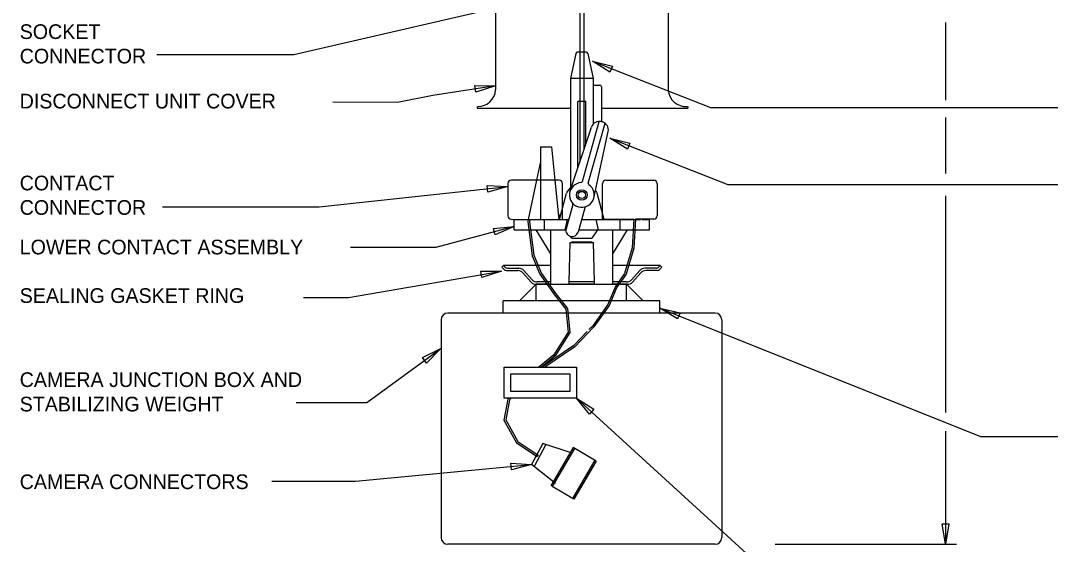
# Model space of a CAD drawing. Extents: x 1299104.6 to 1299141.4, y 239713.3 to 239735.3.
# Drawn here: x 1299120.45 to 1299128.87, y 239721.53 to 239725.82 of the extents above; entities that cross this region are included whole.
import ezdxf

# ---------------------------------------------------------------- set-up
doc = ezdxf.new("R2010")
doc.units = 0
for name, color, linetype in [('DIM TXT', 7, 'Continuous'), ('Level 3', 7, 'Continuous'), ('Level 6', 7, 'Continuous'), ('Level 8', 7, 'Continuous')]:
    doc.layers.add(name, color=color, linetype=linetype)

msp = doc.modelspace()

# ---------------------------------------------------------------- linework, layer by layer
at = {"layer": 'Level 3'}
for p, q in [((1299124.3359, 239726.9924), (1299124.3359, 239725.2509)), ((1299125.7467, 239726.9924), (1299125.7467, 239725.2509)), ((1299124.9918, 239725.55), (1299124.9488, 239725.3448)), ((1299125.0776, 239725.5608), (1299125.005, 239725.5608)), ((1299125.0908, 239725.55), (1299125.1338, 239725.3448)), ((1299125.1338, 239725.3448), (1299124.9488, 239725.3448)), ((1299124.9488, 239725.3448), (1299124.9488, 239724.4533)), ((1299125.1338, 239725.3448), (1299125.1338, 239724.9716)), ((1299125.1338, 239725.2908), (1299125.1878, 239725.2908)), ((1299125.2013, 239725.2773), (1299125.2013, 239724.9922)), ((1299124.1854, 239725.1159), (1299124.1854, 239725.1024)), ((1299124.1854, 239725.1024), (1299124.9488, 239725.1024)), ((1299125.075, 239725.1558), (1299125.0075, 239725.1558)), ((1299125.0075, 239724.6103), (1299125.0075, 239725.1558)), ((1299125.075, 239724.8126), (1299125.075, 239725.1558)), ((1299125.2013, 239725.1024), (1299125.9093, 239725.1024)), ((1299125.9093, 239725.1159), (1299125.9093, 239725.1024)), ((1299124.9436, 239724.4189), (1299125.1203, 239724.9482)), ((1299125.0462, 239724.5029), (1299125.1843, 239724.9943)), ((1299125.0943, 239724.4896), (1299125.2319, 239724.9788)), ((1299125.2022, 239724.9919), (1299125.2091, 239724.99)), ((1299125.1389, 239724.3653), (1299125.2572, 239724.9106)), ((1299124.7038, 239724.7863), (1299124.7929, 239724.7863)), ((1299124.7038, 239724.7863), (1299124.7038, 239724.4862)), ((1299124.7929, 239724.7863), (1299124.8201, 239724.5139)), ((1299124.7038, 239724.6648), (1299124.6715, 239724.5139)), ((1299124.8201, 239724.5139), (1299124.4639, 239724.5139)), ((1299124.6715, 239724.5139), (1299124.6025, 239724.1923)), ((1299124.8564, 239724.5139), (1299124.8201, 239724.5139)), ((1299124.8201, 239724.5139), (1299124.8523, 239724.1923)), ((1299125.2383, 239724.5139), (1299125.6308, 239724.5139)), ((1299124.4369, 239724.4869), (1299124.4369, 239724.2214)), ((1299124.7038, 239724.4862), (1299124.7038, 239724.1923)), ((1299124.8834, 239724.1923), (1299124.8834, 239724.4869)), ((1299125.2113, 239724.1923), (1299125.2113, 239724.4869)), ((1299125.6578, 239724.4869), (1299125.6578, 239724.2214)), ((1299124.859, 239724.1923), (1299124.9164, 239724.4083)), ((1299125.2235, 239724.1923), (1299125.1662, 239724.4083)), ((1299124.9673, 239724.3137), (1299124.913, 239724.1158)), ((1299125.0649, 239724.287), (1299125.0106, 239724.0891)), ((1299124.4638, 239724.1944), (1299124.8834, 239724.1923)), ((1299124.4878, 239724.1059), (1299124.4878, 239724.1923)), ((1299124.4878, 239724.1923), (1299124.934, 239724.1923)), ((1299124.5975, 239724.1937), (1299124.6358, 239723.895)), ((1299124.6111, 239724.1937), (1299124.649, 239723.8986)), ((1299124.7319, 239724.1923), (1299124.7319, 239724.1059)), ((1299124.8523, 239724.2301), (1299124.8691, 239724.2301)), ((1299124.8523, 239724.2301), (1299124.8523, 239724.1923)), ((1299124.9063, 239724.1059), (1299124.9245, 239724.1923)), ((1299125.039, 239724.1923), (1299125.5197, 239724.1923)), ((1299125.1763, 239724.1059), (1299125.1581, 239724.1923)), ((1299125.4661, 239724.1936), (1299125.2113, 239724.1923)), ((1299125.3507, 239724.1923), (1299125.3507, 239724.1059)), ((1299125.4661, 239724.1936), (1299125.4527, 239723.9603)), ((1299125.4796, 239724.1936), (1299125.4661, 239723.9579)), ((1299125.6309, 239724.1944), (1299125.4796, 239724.1936)), ((1299125.5333, 239724.1923), (1299125.5948, 239724.1923)), ((1299125.5948, 239724.1059), (1299125.5948, 239724.1923)), ((1299124.4878, 239724.1059), (1299124.9113, 239724.1059)), ((1299124.7888, 239723.9102), (1299124.6673, 239724.1059)), ((1299124.7888, 239723.6807), (1299124.7888, 239724.1059)), ((1299125.0152, 239724.1059), (1299125.5948, 239724.1059)), ((1299125.1695, 239724.1059), (1299125.1223, 239724.0384)), ((1299125.2937, 239723.9102), (1299125.4152, 239724.1059)), ((1299125.2937, 239723.6807), (1299125.2937, 239724.1059)), ((1299124.9373, 239723.6807), (1299124.9468, 239724.0047)), ((1299124.9468, 239724.0047), (1299125.1358, 239724.0047)), ((1299124.9484, 239724.0536), (1299124.9484, 239724.0536)), ((1299124.9603, 239724.0384), (1299124.9499, 239724.0532)), ((1299125.1257, 239724.0056), (1299124.9569, 239724.0056)), ((1299124.9603, 239724.0384), (1299125.1223, 239724.0384)), ((1299125.1452, 239723.6807), (1299125.1358, 239724.0047)), ((1299125.4527, 239723.9603), (1299125.3909, 239723.7503)), ((1299125.4661, 239723.9579), (1299125.4032, 239723.7443)), ((1299124.6358, 239723.895), (1299124.6988, 239723.744)), ((1299124.649, 239723.8986), (1299124.7107, 239723.7506)), ((1299124.4005, 239723.8157), (1299124.3865, 239723.803)), ((1299124.3865, 239723.803), (1299124.4048, 239723.7827)), ((1299124.4005, 239723.8157), (1299124.4132, 239723.8016)), ((1299124.7888, 239723.8157), (1299124.4005, 239723.8157)), ((1299124.4249, 239723.7738), (1299124.5178, 239723.7738)), ((1299124.4333, 239723.7927), (1299124.5262, 239723.7927)), ((1299124.5579, 239723.756), (1299124.627, 239723.6796)), ((1299124.5663, 239723.7749), (1299124.6354, 239723.6985)), ((1299124.7107, 239723.7506), (1299124.8287, 239723.5832)), ((1299125.682, 239723.8157), (1299125.2937, 239723.8157)), ((1299125.3909, 239723.7503), (1299125.3163, 239723.6447)), ((1299125.4032, 239723.7443), (1299125.3282, 239723.6381)), ((1299125.5163, 239723.7749), (1299125.4472, 239723.6985)), ((1299125.5247, 239723.756), (1299125.4556, 239723.6796)), ((1299125.6493, 239723.7927), (1299125.5564, 239723.7927)), ((1299125.6577, 239723.7738), (1299125.5648, 239723.7738)), ((1299125.682, 239723.8157), (1299125.6694, 239723.8016)), ((1299125.6961, 239723.803), (1299125.6778, 239723.7827)), ((1299125.682, 239723.8157), (1299125.6961, 239723.803)), ((1299124.668, 239723.6618), (1299124.5323, 239723.5268)), ((1299124.7888, 239723.6618), (1299124.667, 239723.6618)), ((1299124.668, 239723.6618), (1299125.4078, 239723.6618)), ((1299124.668, 239723.5268), (1299124.668, 239723.6618)), ((1299124.7888, 239723.6807), (1299124.6754, 239723.6807)), ((1299124.6988, 239723.744), (1299124.8179, 239723.5751)), ((1299124.7888, 239723.6618), (1299124.7888, 239723.6807)), ((1299125.1452, 239723.6807), (1299124.9373, 239723.6807)), ((1299124.9373, 239723.6618), (1299124.9373, 239723.6807)), ((1299125.1452, 239723.6618), (1299124.9373, 239723.6618)), ((1299125.1452, 239723.6618), (1299125.1452, 239723.6807)), ((1299125.2937, 239723.6618), (1299125.2937, 239723.6807)), ((1299125.4072, 239723.6807), (1299125.2937, 239723.6807)), ((1299125.4155, 239723.6618), (1299125.2937, 239723.6618)), ((1299125.4078, 239723.5268), (1299125.4078, 239723.6618)), ((1299125.4078, 239723.6618), (1299125.5434, 239723.5268)), ((1299124.8287, 239723.5832), (1299124.9234, 239723.4634)), ((1299125.3163, 239723.6447), (1299125.2539, 239723.4952)), ((1299125.3282, 239723.6381), (1299125.2658, 239723.4886)), ((1299124.3966, 239723.4256), (1299124.3966, 239723.5268)), ((1299125.6791, 239723.5268), (1299124.3966, 239723.5268)), ((1299124.8179, 239723.5751), (1299124.9103, 239723.4582)), ((1299125.2539, 239723.4952), (1299125.1299, 239723.3218)), ((1299125.6791, 239723.4256), (1299125.6791, 239723.5268)), ((1299126.1314, 239723.4256), (1299123.9444, 239723.4256)), ((1299124.9103, 239723.4582), (1299124.9286, 239723.2693)), ((1299124.9234, 239723.4634), (1299124.9425, 239723.266)), ((1299125.2658, 239723.4886), (1299125.1403, 239723.3132)), ((1299123.8904, 239723.3716), (1299123.8904, 239721.5896)), ((1299126.1854, 239723.3716), (1299126.1854, 239721.5896)), ((1299124.9286, 239723.2693), (1299124.8119, 239723.0853)), ((1299124.9425, 239723.266), (1299124.8222, 239723.0763)), ((1299125.0852, 239723.2754), (1299124.9748, 239723.1608)), ((1299125.1403, 239723.3132), (1299124.9836, 239723.1504)), ((1299125.1299, 239723.3218), (1299125.0997, 239723.2905)), ((1299124.9748, 239723.1608), (1299124.7138, 239722.9835)), ((1299124.8119, 239723.0853), (1299124.6903, 239722.9835)), ((1299124.8222, 239723.0763), (1299124.7114, 239722.9835)), ((1299124.9836, 239723.1504), (1299124.7379, 239722.9835)), ((1299124.4366, 239722.7227), (1299124.4046, 239722.5502)), ((1299124.4491, 239722.7164), (1299124.4187, 239722.5525)), ((1299124.444, 239722.7309), (1299124.4366, 239722.7227)), ((1299124.4622, 239722.7309), (1299124.4491, 239722.7164)), ((1299124.4046, 239722.5502), (1299124.5063, 239722.366)), ((1299124.4187, 239722.5525), (1299124.5166, 239722.3754)), ((1299124.5063, 239722.366), (1299124.6761, 239722.253)), ((1299124.5166, 239722.3754), (1299124.6836, 239722.2642)), ((1299124.7218, 239722.3602), (1299124.6294, 239722.1883)), ((1299124.7478, 239722.3516), (1299124.651, 239722.1713)), ((1299124.9609, 239722.2813), (1299124.7218, 239722.3602)), ((1299124.9699, 239722.3265), (1299124.7866, 239722.0139)), ((1299124.9815, 239722.3197), (1299124.7982, 239722.007)), ((1299125.1597, 239722.2152), (1299124.9699, 239722.3265)), ((1299124.6836, 239722.2642), (1299124.6761, 239722.253)), ((1299124.8272, 239722.0325), (1299124.6294, 239722.1883)), ((1299125.148, 239722.222), (1299124.9647, 239721.9094)), ((1299125.1597, 239722.2152), (1299124.9764, 239721.9026)), ((1299124.9764, 239721.9026), (1299124.7982, 239722.007)), ((1299126.1314, 239721.5356), (1299123.9444, 239721.5356))]:
    msp.add_line(p, q, dxfattribs=at)
for points in [[(1299124.4063, 239722.9835), (1299124.9987, 239722.9835), (1299124.9987, 239722.7309), (1299124.4063, 239722.7309)], [(1299124.4608, 239722.9291), (1299124.9443, 239722.9291), (1299124.9443, 239722.7853), (1299124.4608, 239722.7853)]]:
    msp.add_lwpolyline(points, close=True, dxfattribs=at)
for radius in [0.0432, 0.0297]:
    msp.add_circle((1299125.0413, 239724.3921), radius, dxfattribs=at)
for centre, radius, start, end in [((1299125.005, 239725.5473), 0.0135, 90, 168.17452), ((1299125.0776, 239725.5473), 0.0135, 11.82548, 90), ((1299125.1878, 239725.2773), 0.0135, 0, 90), ((1299124.1909, 239725.2614), 0.1454, 270.23601, 355.89039), ((1299125.8925, 239725.2617), 0.1462, 184.23639, 274.23639), ((1299125.1843, 239724.9268), 0.0675, 74.65494, 161.5441), ((1299125.1912, 239724.9249), 0.0675, 347.76578, 74.65494), ((1299124.4639, 239724.4869), 0.027, 90, 180), ((1299124.8564, 239724.4869), 0.027, 0, 90), ((1299125.0332, 239724.5066), 0.0135, 274.03295, 344.30105), ((1299125.2383, 239724.4869), 0.027, 90, 180), ((1299125.6308, 239724.4869), 0.027, 0, 90), ((1299125.0413, 239724.3526), 0.1368, 127.72918, 155.93881), ((1299125.0413, 239724.3921), 0.1012, 94.03295, 54.85197), ((1299125.1073, 239724.4859), 0.0135, 164.30105, 234.85197), ((1299125.0413, 239724.3526), 0.1368, 24.06119, 35.0803), ((1299124.9543, 239724.3173), 0.0135, 344.65494, 40.68046), ((1299125.0779, 239724.2834), 0.0135, 108.62941, 164.65494), ((1299124.4639, 239724.2214), 0.027, 180, 269.7176), ((1299125.6308, 239724.2214), 0.027, 270.2824, 0), ((1299124.9618, 239724.1024), 0.0506, 164.65494, 254.65494), ((1299124.9618, 239724.1024), 0.0506, 254.65494, 344.65494), ((1299124.4249, 239723.8008), 0.027, 222.08916, 270), ((1299124.4333, 239723.8197), 0.027, 222.08916, 270), ((1299124.5178, 239723.7198), 0.054, 42.10142, 90), ((1299124.5262, 239723.7387), 0.054, 42.10142, 90), ((1299125.5564, 239723.7387), 0.054, 90, 137.89858), ((1299125.5648, 239723.7198), 0.054, 90, 137.89858), ((1299125.6493, 239723.8197), 0.027, 270, 317.91084), ((1299125.6577, 239723.8008), 0.027, 270, 317.91084), ((1299124.667, 239723.7158), 0.054, 222.10142, 270), ((1299124.6754, 239723.7347), 0.054, 222.10142, 270), ((1299125.4072, 239723.7347), 0.054, 270, 317.89858), ((1299125.4155, 239723.7158), 0.054, 270, 317.89858), ((1299123.9444, 239723.3716), 0.054, 90, 180), ((1299126.1314, 239723.3716), 0.054, 0, 90), ((1299123.9444, 239721.5896), 0.054, 180, 270), ((1299126.1314, 239721.5896), 0.054, 270, 0)]:
    msp.add_arc(centre, radius, start, end, dxfattribs=at)
at = {"layer": 'Level 6'}
for p, q in [((1299125.0244, 239727.6536), (1299125.0244, 239724.6609)), ((1299125.0582, 239727.6704), (1299125.0582, 239724.762))]:
    msp.add_line(p, q, dxfattribs=at)
at = {"layer": 'Level 8'}
for p, q in [((1299128.0143, 239725.803), (1299128.0143, 239725.1682)), ((1299128.0143, 239725.0248), (1299128.0143, 239724.568)), ((1299122.8923, 239724.2946), (1299124.4369, 239724.4603)), ((1299128.0143, 239724.3846), (1299128.0143, 239722.6125)), ((1299121.6106, 239724.2946), (1299122.8923, 239724.2946)), ((1299123.1338, 239723.5548), (1299124.3831, 239723.7703)), ((1299122.7651, 239723.5548), (1299123.1338, 239723.5548)), ((1299123.2828, 239722.6934), (1299123.8887, 239723.1375)), ((1299122.7055, 239722.6934), (1299123.2828, 239722.6934)), ((1299128.0143, 239722.4598), (1299128.0143, 239721.5356)), ((1299123.1902, 239722.0519), (1299124.6294, 239722.1883)), ((1299122.5062, 239722.0519), (1299123.1902, 239722.0519)), ((1299126.6214, 239721.5356), (1299128.1042, 239721.5356))]:
    msp.add_line(p, q, dxfattribs=at)
for points in [[(1299124.4015, 239725.9331), (1299122.685, 239725.5375), (1299121.5664, 239725.5375), (1299121.5664, 239725.5375)], [(1299125.1287, 239725.4876), (1299126.0936, 239725.1077), (1299132.0486, 239725.1077)], [(1299124.3359, 239725.2847), (1299123.8221, 239725.2072), (1299123.5348, 239725.1489), (1299123.0049, 239725.1504)], [(1299125.2711, 239724.8573), (1299126.236, 239724.4774), (1299132.0486, 239724.4774)], [(1299124.4878, 239724.1347), (1299123.8484, 239723.9627), (1299123.1907, 239723.9627), (1299123.1499, 239723.9627)], [(1299125.6784, 239723.4656), (1299128.3026, 239722.4172), (1299132.0486, 239722.4172)], [(1299124.9987, 239722.7309), (1299126.6402, 239721.2281), (1299132.0486, 239721.2281)]]:
    msp.add_lwpolyline(points, dxfattribs=at)
for points in [[(1299125.2927, 239725.4467), (1299125.2712, 239725.3967), (1299125.1287, 239725.4876)], [(1299124.175, 239725.233), (1299124.1669, 239725.2868), (1299124.3359, 239725.2847)], [(1299125.4351, 239724.8164), (1299125.4137, 239724.7664), (1299125.2711, 239724.8573)], [(1299124.2736, 239724.4165), (1299124.2682, 239724.4706), (1299124.4369, 239724.4603)], [(1299124.333, 239724.0667), (1299124.3195, 239724.1193), (1299124.4878, 239724.1347)], [(1299124.2229, 239723.7164), (1299124.2141, 239723.77), (1299124.3831, 239723.7703)], [(1299125.8442, 239723.4291), (1299125.8241, 239723.3785), (1299125.6791, 239723.4654)], [(1299123.7696, 239723.0175), (1299123.7377, 239723.0615), (1299123.8887, 239723.1375)], [(1299125.1405, 239722.6388), (1299125.1039, 239722.5986), (1299124.9987, 239722.7309)], [(1299124.4664, 239722.1437), (1299124.4607, 239722.1977), (1299124.6294, 239722.1883)], [(1299127.9871, 239721.7024), (1299128.0415, 239721.7024), (1299128.0143, 239721.5356)]]:
    msp.add_lwpolyline(points, close=True, dxfattribs=at)

# ---------------------------------------------------------------- texts
at = {"layer": 'DIM TXT'}
for s, p in [('SOCKET', (1299120.444, 239725.6682)), ('CONNECTOR', (1299120.444, 239725.4682)), ('DISCONNECT UNIT COVER', (1299120.444, 239725.1001)), ('CONTACT', (1299120.444, 239724.4301)), ('CONNECTOR', (1299120.444, 239724.2301)), ('LOWER CONTACT ASSEMBLY', (1299120.444, 239723.9063)), ('SEALING GASKET RING', (1299120.444, 239723.5092)), ('CAMERA JUNCTION BOX AND ', (1299120.444, 239722.8215)), ('STABILIZING WEIGHT', (1299120.444, 239722.6215)), ('CAMERA CONNECTORS', (1299120.444, 239721.9862))]:
    msp.add_text(s, height=0.12, dxfattribs=at).set_placement(p)

doc.saveas('drawing.dxf')
